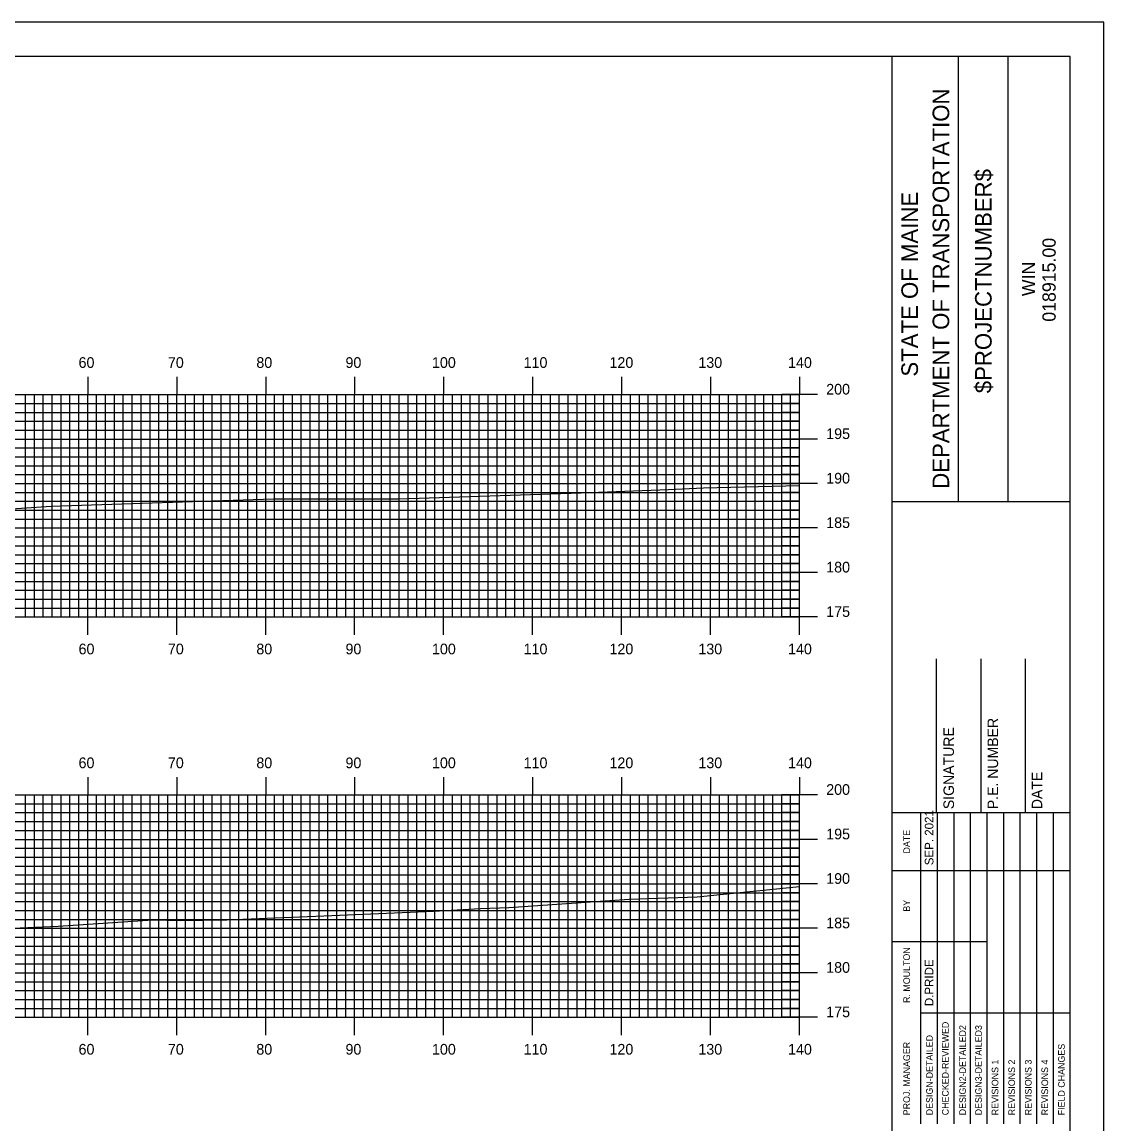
# Model space of a CAD drawing. Extents: x 1822785 to 1823129, y 442591 to 442811.
# Drawn here: x 1823003.9 to 1823125.5, y 442686.7 to 442810.5 of the extents above; entities that cross this region are included whole.
import ezdxf

# ---------------------------------------------------------------- set-up
doc = ezdxf.new("R2010")
doc.units = 0
for name, color, linetype in [('BORDER', 7, 'Continuous'), ('H_V ANNOTATION', 7, 'Continuous'), ('MAJOR', 7, 'Continuous'), ('MINOR', 7, 'Continuous'), ('PLOT BOUNDARY', 7, 'Continuous'), ('S_Roadway_Centerline', 7, 'Continuous')]:
    doc.layers.add(name, color=color, linetype=linetype)

msp = doc.modelspace()

# ---------------------------------------------------------------- linework, layer by layer
at = {"layer": 'BORDER'}
for p, q in [((1823101.68, 442596.67), (1823101.68, 442806.67)), ((1823109.14, 442756.66), (1823109.14, 442806.66)), ((1823114.73, 442756.66), (1823114.73, 442806.66)), ((1823101.68, 442756.65), (1823121.68, 442756.65)), ((1823106.68, 442721.67), (1823106.68, 442738.97)), ((1823111.68, 442721.67), (1823111.68, 442738.97)), ((1823116.68, 442721.67), (1823116.68, 442738.97)), ((1823101.68, 442721.67), (1823121.68, 442721.67))]:
    msp.add_line(p, q, dxfattribs=at)
msp.add_lwpolyline([(1822801.68, 442596.67), (1823121.68, 442596.67), (1823121.68, 442806.67), (1822801.68, 442806.67)], close=True, dxfattribs=at)
for points in [[(1823104.91, 442715.17), (1823104.91, 442721.67)], [(1823106.78, 442686.68), (1823106.78, 442721.67)], [(1823108.64, 442721.67), (1823108.64, 442686.68)], [(1823110.5, 442686.68), (1823110.5, 442721.67)], [(1823112.37, 442686.68), (1823112.37, 442721.67)], [(1823114.23, 442686.68), (1823114.23, 442721.67)], [(1823116.09, 442686.68), (1823116.09, 442721.67)], [(1823117.96, 442686.68), (1823117.96, 442721.67)], [(1823119.82, 442686.68), (1823119.82, 442721.67)], [(1823104.91, 442686.68), (1823104.91, 442720.26)], [(1823101.68, 442715.17), (1823121.68, 442715.17)], [(1823101.68, 442707.17), (1823104.91, 442707.17)], [(1823104.91, 442707.17), (1823112.37, 442707.17)], [(1823104.91, 442699.17), (1823121.68, 442699.17)]]:
    msp.add_lwpolyline(points, dxfattribs=at)
at = {"layer": 'MAJOR'}
for p, q in [((1823011.28, 442770.67), (1823011.28, 442768.67)), ((1823021.28, 442770.67), (1823021.28, 442768.67)), ((1823031.28, 442770.67), (1823031.28, 442768.67)), ((1823041.28, 442770.67), (1823041.28, 442768.67)), ((1823051.28, 442770.67), (1823051.28, 442768.67)), ((1823061.28, 442770.67), (1823061.28, 442768.67)), ((1823071.28, 442770.67), (1823071.28, 442768.67)), ((1823081.28, 442770.67), (1823081.28, 442768.67)), ((1823091.28, 442770.67), (1823091.28, 442768.67)), ((1822811.28, 442768.67), (1823091.28, 442768.67)), ((1822811.28, 442768.67), (1823091.28, 442768.67)), ((1823011.28, 442743.67), (1823011.28, 442768.67)), ((1823021.28, 442743.67), (1823021.28, 442768.67)), ((1823031.28, 442743.67), (1823031.28, 442768.67)), ((1823041.28, 442743.67), (1823041.28, 442768.67)), ((1823051.28, 442743.67), (1823051.28, 442768.67)), ((1823061.28, 442743.67), (1823061.28, 442768.67)), ((1823071.28, 442743.67), (1823071.28, 442768.67)), ((1823081.28, 442743.67), (1823081.28, 442768.67)), ((1823093.29, 442768.67), (1823089.28, 442768.67)), ((1823091.28, 442743.67), (1823091.28, 442768.67)), ((1823091.28, 442743.67), (1823091.28, 442768.67)), ((1822811.28, 442763.67), (1823091.28, 442763.67)), ((1823093.29, 442763.67), (1823089.28, 442763.67)), ((1822811.28, 442758.67), (1823091.28, 442758.67)), ((1823093.29, 442758.67), (1823089.28, 442758.67)), ((1822811.28, 442753.67), (1823091.28, 442753.67)), ((1823093.29, 442753.67), (1823089.28, 442753.67)), ((1822811.28, 442748.67), (1823091.28, 442748.67)), ((1823093.29, 442748.67), (1823089.28, 442748.67)), ((1822811.28, 442743.67), (1823091.28, 442743.67)), ((1822811.28, 442743.67), (1823091.28, 442743.67)), ((1823011.28, 442741.66), (1823011.28, 442743.67)), ((1823021.28, 442741.66), (1823021.28, 442743.67)), ((1823031.28, 442741.66), (1823031.28, 442743.67)), ((1823041.28, 442741.66), (1823041.28, 442743.67)), ((1823051.28, 442741.66), (1823051.28, 442743.67)), ((1823061.28, 442741.66), (1823061.28, 442743.67)), ((1823071.28, 442741.66), (1823071.28, 442743.67)), ((1823081.28, 442741.66), (1823081.28, 442743.67)), ((1823093.29, 442743.67), (1823089.28, 442743.67)), ((1823091.28, 442741.66), (1823091.28, 442743.67)), ((1823011.28, 442725.67), (1823011.28, 442723.67)), ((1823021.28, 442725.67), (1823021.28, 442723.67)), ((1823031.28, 442725.67), (1823031.28, 442723.67)), ((1823041.28, 442725.67), (1823041.28, 442723.67)), ((1823051.28, 442725.67), (1823051.28, 442723.67)), ((1823061.28, 442725.67), (1823061.28, 442723.67)), ((1823071.28, 442725.67), (1823071.28, 442723.67)), ((1823081.28, 442725.67), (1823081.28, 442723.67)), ((1823091.28, 442725.67), (1823091.28, 442723.67)), ((1822811.28, 442723.67), (1823091.28, 442723.67)), ((1822811.28, 442723.67), (1823091.28, 442723.67)), ((1823011.28, 442698.67), (1823011.28, 442723.67)), ((1823021.28, 442698.67), (1823021.28, 442723.67)), ((1823031.28, 442698.67), (1823031.28, 442723.67)), ((1823041.28, 442698.67), (1823041.28, 442723.67)), ((1823051.28, 442698.67), (1823051.28, 442723.67)), ((1823061.28, 442698.67), (1823061.28, 442723.67)), ((1823071.28, 442698.67), (1823071.28, 442723.67)), ((1823081.28, 442698.67), (1823081.28, 442723.67)), ((1823093.29, 442723.67), (1823089.28, 442723.67)), ((1823091.28, 442698.67), (1823091.28, 442723.67)), ((1823091.28, 442698.67), (1823091.28, 442723.67)), ((1822811.28, 442718.67), (1823091.28, 442718.67)), ((1823093.29, 442718.67), (1823089.28, 442718.67)), ((1822811.28, 442713.67), (1823091.28, 442713.67)), ((1823093.29, 442713.67), (1823089.28, 442713.67)), ((1822811.28, 442708.67), (1823091.28, 442708.67)), ((1823093.29, 442708.67), (1823089.28, 442708.67)), ((1822811.28, 442703.67), (1823091.28, 442703.67)), ((1823093.29, 442703.67), (1823089.28, 442703.67)), ((1822811.28, 442698.67), (1823091.28, 442698.67)), ((1822811.28, 442698.67), (1823091.28, 442698.67)), ((1823011.28, 442696.66), (1823011.28, 442698.67)), ((1823021.28, 442696.66), (1823021.28, 442698.67)), ((1823031.28, 442696.66), (1823031.28, 442698.67)), ((1823041.28, 442696.66), (1823041.28, 442698.67)), ((1823051.28, 442696.66), (1823051.28, 442698.67)), ((1823061.28, 442696.66), (1823061.28, 442698.67)), ((1823071.28, 442696.66), (1823071.28, 442698.67)), ((1823081.28, 442696.66), (1823081.28, 442698.67)), ((1823093.29, 442698.67), (1823089.28, 442698.67)), ((1823091.28, 442696.66), (1823091.28, 442698.67))]:
    msp.add_line(p, q, dxfattribs=at)
at = {"layer": 'MINOR'}
for p, q in [((1823004.28, 442743.67), (1823004.28, 442768.67)), ((1823005.28, 442743.67), (1823005.28, 442768.67)), ((1823006.28, 442743.67), (1823006.28, 442768.67)), ((1823007.28, 442743.67), (1823007.28, 442768.67)), ((1823008.28, 442743.67), (1823008.28, 442768.67)), ((1823009.28, 442743.67), (1823009.28, 442768.67)), ((1823010.28, 442743.67), (1823010.28, 442768.67)), ((1823012.28, 442743.67), (1823012.28, 442768.67)), ((1823013.28, 442743.67), (1823013.28, 442768.67)), ((1823014.28, 442743.67), (1823014.28, 442768.67)), ((1823015.28, 442743.67), (1823015.28, 442768.67)), ((1823016.28, 442743.67), (1823016.28, 442768.67)), ((1823017.28, 442743.67), (1823017.28, 442768.67)), ((1823018.28, 442743.67), (1823018.28, 442768.67)), ((1823019.28, 442743.67), (1823019.28, 442768.67)), ((1823020.28, 442743.67), (1823020.28, 442768.67)), ((1823022.28, 442743.67), (1823022.28, 442768.67)), ((1823023.28, 442743.67), (1823023.28, 442768.67)), ((1823024.28, 442743.67), (1823024.28, 442768.67)), ((1823025.28, 442743.67), (1823025.28, 442768.67)), ((1823026.28, 442743.67), (1823026.28, 442768.67)), ((1823027.28, 442743.67), (1823027.28, 442768.67)), ((1823028.28, 442743.67), (1823028.28, 442768.67)), ((1823029.28, 442743.67), (1823029.28, 442768.67)), ((1823030.28, 442743.67), (1823030.28, 442768.67)), ((1823032.28, 442743.67), (1823032.28, 442768.67)), ((1823033.28, 442743.67), (1823033.28, 442768.67)), ((1823034.28, 442743.67), (1823034.28, 442768.67)), ((1823035.28, 442743.67), (1823035.28, 442768.67)), ((1823036.28, 442743.67), (1823036.28, 442768.67)), ((1823037.28, 442743.67), (1823037.28, 442768.67)), ((1823038.28, 442743.67), (1823038.28, 442768.67)), ((1823039.28, 442743.67), (1823039.28, 442768.67)), ((1823040.28, 442743.67), (1823040.28, 442768.67)), ((1823042.28, 442743.67), (1823042.28, 442768.67)), ((1823043.28, 442743.67), (1823043.28, 442768.67)), ((1823044.28, 442743.67), (1823044.28, 442768.67)), ((1823045.28, 442743.67), (1823045.28, 442768.67)), ((1823046.28, 442743.67), (1823046.28, 442768.67)), ((1823047.28, 442743.67), (1823047.28, 442768.67)), ((1823048.28, 442743.67), (1823048.28, 442768.67)), ((1823049.28, 442743.67), (1823049.28, 442768.67)), ((1823050.28, 442743.67), (1823050.28, 442768.67)), ((1823052.28, 442743.67), (1823052.28, 442768.67)), ((1823053.28, 442743.67), (1823053.28, 442768.67)), ((1823054.28, 442743.67), (1823054.28, 442768.67)), ((1823055.28, 442743.67), (1823055.28, 442768.67)), ((1823056.28, 442743.67), (1823056.28, 442768.67)), ((1823057.28, 442743.67), (1823057.28, 442768.67)), ((1823058.28, 442743.67), (1823058.28, 442768.67)), ((1823059.28, 442743.67), (1823059.28, 442768.67)), ((1823060.28, 442743.67), (1823060.28, 442768.67)), ((1823062.28, 442743.67), (1823062.28, 442768.67)), ((1823063.28, 442743.67), (1823063.28, 442768.67)), ((1823064.28, 442743.67), (1823064.28, 442768.67)), ((1823065.28, 442743.67), (1823065.28, 442768.67)), ((1823066.28, 442743.67), (1823066.28, 442768.67)), ((1823067.28, 442743.67), (1823067.28, 442768.67)), ((1823068.28, 442743.67), (1823068.28, 442768.67)), ((1823069.28, 442743.67), (1823069.28, 442768.67)), ((1823070.28, 442743.67), (1823070.28, 442768.67)), ((1823072.28, 442743.67), (1823072.28, 442768.67)), ((1823073.28, 442743.67), (1823073.28, 442768.67)), ((1823074.28, 442743.67), (1823074.28, 442768.67)), ((1823075.28, 442743.67), (1823075.28, 442768.67)), ((1823076.28, 442743.67), (1823076.28, 442768.67)), ((1823077.28, 442743.67), (1823077.28, 442768.67)), ((1823078.28, 442743.67), (1823078.28, 442768.67)), ((1823079.28, 442743.67), (1823079.28, 442768.67)), ((1823080.28, 442743.67), (1823080.28, 442768.67)), ((1823082.28, 442743.67), (1823082.28, 442768.67)), ((1823083.28, 442743.67), (1823083.28, 442768.67)), ((1823084.28, 442743.67), (1823084.28, 442768.67)), ((1823085.28, 442743.67), (1823085.28, 442768.67)), ((1823086.28, 442743.67), (1823086.28, 442768.67)), ((1823087.28, 442743.67), (1823087.28, 442768.67)), ((1823088.28, 442743.67), (1823088.28, 442768.67)), ((1823089.28, 442743.67), (1823089.28, 442768.67)), ((1823090.28, 442743.67), (1823090.28, 442768.67)), ((1822811.28, 442767.67), (1823091.28, 442767.67)), ((1823091.28, 442767.67), (1823089.28, 442767.67)), ((1822811.28, 442766.67), (1823091.28, 442766.67)), ((1823091.28, 442766.67), (1823089.28, 442766.67)), ((1822811.28, 442765.67), (1823091.28, 442765.67)), ((1823091.28, 442765.67), (1823089.28, 442765.67)), ((1822811.28, 442764.67), (1823091.28, 442764.67)), ((1823091.28, 442764.67), (1823089.28, 442764.67)), ((1822811.28, 442762.67), (1823091.28, 442762.67)), ((1823091.28, 442762.67), (1823089.28, 442762.67)), ((1822811.28, 442761.67), (1823091.28, 442761.67)), ((1823091.28, 442761.67), (1823089.28, 442761.67)), ((1822811.28, 442760.67), (1823091.28, 442760.67)), ((1823091.28, 442760.67), (1823089.28, 442760.67)), ((1822811.28, 442759.67), (1823091.28, 442759.67)), ((1823091.28, 442759.67), (1823089.28, 442759.67)), ((1822811.28, 442757.67), (1823091.28, 442757.67)), ((1823091.28, 442757.67), (1823089.28, 442757.67)), ((1822811.28, 442756.67), (1823091.28, 442756.67)), ((1823091.28, 442756.67), (1823089.28, 442756.67)), ((1822811.28, 442755.67), (1823091.28, 442755.67)), ((1823091.28, 442755.67), (1823089.28, 442755.67)), ((1822811.28, 442754.67), (1823091.28, 442754.67)), ((1823091.28, 442754.67), (1823089.28, 442754.67)), ((1822811.28, 442752.67), (1823091.28, 442752.67)), ((1823091.28, 442752.67), (1823089.28, 442752.67)), ((1822811.28, 442751.67), (1823091.28, 442751.67)), ((1823091.28, 442751.67), (1823089.28, 442751.67)), ((1822811.28, 442750.67), (1823091.28, 442750.67)), ((1823091.28, 442750.67), (1823089.28, 442750.67)), ((1822811.28, 442749.67), (1823091.28, 442749.67)), ((1823091.28, 442749.67), (1823089.28, 442749.67)), ((1822811.28, 442747.67), (1823091.28, 442747.67)), ((1823091.28, 442747.67), (1823089.28, 442747.67)), ((1822811.28, 442746.67), (1823091.28, 442746.67)), ((1823091.28, 442746.67), (1823089.28, 442746.67)), ((1822811.28, 442745.67), (1823091.28, 442745.67)), ((1823091.28, 442745.67), (1823089.28, 442745.67)), ((1822811.28, 442744.67), (1823091.28, 442744.67)), ((1823091.28, 442744.67), (1823089.28, 442744.67)), ((1823004.28, 442698.67), (1823004.28, 442723.67)), ((1823005.28, 442698.67), (1823005.28, 442723.67)), ((1823006.28, 442698.67), (1823006.28, 442723.67)), ((1823007.28, 442698.67), (1823007.28, 442723.67)), ((1823008.28, 442698.67), (1823008.28, 442723.67)), ((1823009.28, 442698.67), (1823009.28, 442723.67)), ((1823010.28, 442698.67), (1823010.28, 442723.67)), ((1823012.28, 442698.67), (1823012.28, 442723.67)), ((1823013.28, 442698.67), (1823013.28, 442723.67)), ((1823014.28, 442698.67), (1823014.28, 442723.67)), ((1823015.28, 442698.67), (1823015.28, 442723.67)), ((1823016.28, 442698.67), (1823016.28, 442723.67)), ((1823017.28, 442698.67), (1823017.28, 442723.67)), ((1823018.28, 442698.67), (1823018.28, 442723.67)), ((1823019.28, 442698.67), (1823019.28, 442723.67)), ((1823020.28, 442698.67), (1823020.28, 442723.67)), ((1823022.28, 442698.67), (1823022.28, 442723.67)), ((1823023.28, 442698.67), (1823023.28, 442723.67)), ((1823024.28, 442698.67), (1823024.28, 442723.67)), ((1823025.28, 442698.67), (1823025.28, 442723.67)), ((1823026.28, 442698.67), (1823026.28, 442723.67)), ((1823027.28, 442698.67), (1823027.28, 442723.67)), ((1823028.28, 442698.67), (1823028.28, 442723.67)), ((1823029.28, 442698.67), (1823029.28, 442723.67)), ((1823030.28, 442698.67), (1823030.28, 442723.67)), ((1823032.28, 442698.67), (1823032.28, 442723.67)), ((1823033.28, 442698.67), (1823033.28, 442723.67)), ((1823034.28, 442698.67), (1823034.28, 442723.67)), ((1823035.28, 442698.67), (1823035.28, 442723.67)), ((1823036.28, 442698.67), (1823036.28, 442723.67)), ((1823037.28, 442698.67), (1823037.28, 442723.67)), ((1823038.28, 442698.67), (1823038.28, 442723.67)), ((1823039.28, 442698.67), (1823039.28, 442723.67)), ((1823040.28, 442698.67), (1823040.28, 442723.67)), ((1823042.28, 442698.67), (1823042.28, 442723.67)), ((1823043.28, 442698.67), (1823043.28, 442723.67)), ((1823044.28, 442698.67), (1823044.28, 442723.67)), ((1823045.28, 442698.67), (1823045.28, 442723.67)), ((1823046.28, 442698.67), (1823046.28, 442723.67)), ((1823047.28, 442698.67), (1823047.28, 442723.67)), ((1823048.28, 442698.67), (1823048.28, 442723.67)), ((1823049.28, 442698.67), (1823049.28, 442723.67)), ((1823050.28, 442698.67), (1823050.28, 442723.67)), ((1823052.28, 442698.67), (1823052.28, 442723.67)), ((1823053.28, 442698.67), (1823053.28, 442723.67)), ((1823054.28, 442698.67), (1823054.28, 442723.67)), ((1823055.28, 442698.67), (1823055.28, 442723.67)), ((1823056.28, 442698.67), (1823056.28, 442723.67)), ((1823057.28, 442698.67), (1823057.28, 442723.67)), ((1823058.28, 442698.67), (1823058.28, 442723.67)), ((1823059.28, 442698.67), (1823059.28, 442723.67)), ((1823060.28, 442698.67), (1823060.28, 442723.67)), ((1823062.28, 442698.67), (1823062.28, 442723.67)), ((1823063.28, 442698.67), (1823063.28, 442723.67)), ((1823064.28, 442698.67), (1823064.28, 442723.67)), ((1823065.28, 442698.67), (1823065.28, 442723.67)), ((1823066.28, 442698.67), (1823066.28, 442723.67)), ((1823067.28, 442698.67), (1823067.28, 442723.67)), ((1823068.28, 442698.67), (1823068.28, 442723.67)), ((1823069.28, 442698.67), (1823069.28, 442723.67)), ((1823070.28, 442698.67), (1823070.28, 442723.67)), ((1823072.28, 442698.67), (1823072.28, 442723.67)), ((1823073.28, 442698.67), (1823073.28, 442723.67)), ((1823074.28, 442698.67), (1823074.28, 442723.67)), ((1823075.28, 442698.67), (1823075.28, 442723.67)), ((1823076.28, 442698.67), (1823076.28, 442723.67)), ((1823077.28, 442698.67), (1823077.28, 442723.67)), ((1823078.28, 442698.67), (1823078.28, 442723.67)), ((1823079.28, 442698.67), (1823079.28, 442723.67)), ((1823080.28, 442698.67), (1823080.28, 442723.67)), ((1823082.28, 442698.67), (1823082.28, 442723.67)), ((1823083.28, 442698.67), (1823083.28, 442723.67)), ((1823084.28, 442698.67), (1823084.28, 442723.67)), ((1823085.28, 442698.67), (1823085.28, 442723.67)), ((1823086.28, 442698.67), (1823086.28, 442723.67)), ((1823087.28, 442698.67), (1823087.28, 442723.67)), ((1823088.28, 442698.67), (1823088.28, 442723.67)), ((1823089.28, 442698.67), (1823089.28, 442723.67)), ((1823090.28, 442698.67), (1823090.28, 442723.67)), ((1822811.28, 442722.67), (1823091.28, 442722.67)), ((1822811.28, 442721.67), (1823091.28, 442721.67)), ((1823091.28, 442722.67), (1823089.28, 442722.67)), ((1823091.28, 442721.67), (1823089.28, 442721.67)), ((1822811.28, 442720.67), (1823091.28, 442720.67)), ((1823091.28, 442720.67), (1823089.28, 442720.67)), ((1822811.28, 442719.67), (1823091.28, 442719.67)), ((1823091.28, 442719.67), (1823089.28, 442719.67)), ((1822811.28, 442717.67), (1823091.28, 442717.67)), ((1822811.28, 442716.67), (1823091.28, 442716.67)), ((1823091.28, 442717.67), (1823089.28, 442717.67)), ((1823091.28, 442716.67), (1823089.28, 442716.67)), ((1822811.28, 442715.67), (1823091.28, 442715.67)), ((1823091.28, 442715.67), (1823089.28, 442715.67)), ((1822811.28, 442714.67), (1823091.28, 442714.67)), ((1823091.28, 442714.67), (1823089.28, 442714.67)), ((1822811.28, 442712.67), (1823091.28, 442712.67)), ((1822811.28, 442711.67), (1823091.28, 442711.67)), ((1823091.28, 442712.67), (1823089.28, 442712.67)), ((1823091.28, 442711.67), (1823089.28, 442711.67)), ((1822811.28, 442710.67), (1823091.28, 442710.67)), ((1823091.28, 442710.67), (1823089.28, 442710.67)), ((1822811.28, 442709.67), (1823091.28, 442709.67)), ((1823091.28, 442709.67), (1823089.28, 442709.67)), ((1822811.28, 442707.67), (1823091.28, 442707.67)), ((1822811.28, 442706.67), (1823091.28, 442706.67)), ((1823091.28, 442707.67), (1823089.28, 442707.67)), ((1823091.28, 442706.67), (1823089.28, 442706.67)), ((1822811.28, 442705.67), (1823091.28, 442705.67)), ((1823091.28, 442705.67), (1823089.28, 442705.67)), ((1822811.28, 442704.67), (1823091.28, 442704.67)), ((1823091.28, 442704.67), (1823089.28, 442704.67)), ((1822811.28, 442702.67), (1823091.28, 442702.67)), ((1822811.28, 442701.67), (1823091.28, 442701.67)), ((1823091.28, 442702.67), (1823089.28, 442702.67)), ((1823091.28, 442701.67), (1823089.28, 442701.67)), ((1822811.28, 442700.67), (1823091.28, 442700.67)), ((1823091.28, 442700.67), (1823089.28, 442700.67)), ((1822811.28, 442699.67), (1823091.28, 442699.67)), ((1823091.28, 442699.67), (1823089.28, 442699.67))]:
    msp.add_line(p, q, dxfattribs=at)
at = {"layer": 'PLOT BOUNDARY'}
msp.add_lwpolyline([(1822785.5, 442590.55), (1823125.5, 442590.55), (1823125.5, 442810.55), (1822785.5, 442810.55)], close=True, dxfattribs=at)
at = {"layer": 'S_Roadway_Centerline'}
for points in [[(1822993.8, 442755.24), (1823007.16, 442756.13), (1823032.15, 442756.93), (1823046.25, 442756.94), (1823066.75, 442757.63), (1823076.57, 442757.99), (1823080.48, 442758.19), (1823091.28, 442758.43)], [(1823003.7, 442708.74), (1823007.94, 442708.92), (1823018.58, 442709.61), (1823021.74, 442709.56), (1823026.92, 442709.63), (1823038.7, 442710.11), (1823050.16, 442710.58), (1823055.44, 442710.9), (1823058.59, 442711), (1823072.13, 442711.94), (1823079.77, 442712.21), (1823091.28, 442713.38)]]:
    msp.add_lwpolyline(points, dxfattribs=at)

# ---------------------------------------------------------------- texts
at = {"layer": 'BORDER'}
for s, height, p in [('DEPARTMENT OF TRANSPORTATION', 1.8635, (1823108.1, 442758.08)), ('$PROJECTNUMBER$', 1.8635, (1823112.87, 442768.82)), ('STATE OF MAINE', 1.8635, (1823104.59, 442770.69)), ('018915.00', 1.491, (1823120.07, 442776.86)), ('WIN', 1.491, (1823117.76, 442779.73)), ('P.E. NUMBER', 1.1811, (1823113.6, 442722.06)), ('SIGNATURE', 1.181, (1823108.64, 442722.06)), ('DATE', 1.181, (1823118.56, 442722.06)), ('SEP. 2021', 0.969, (1823106.33, 442715.76)), ('DATE', 0.743, (1823103.69, 442717.08)), ('BY', 0.743, (1823103.69, 442710.54)), ('R. MOULTON', 0.745, (1823103.69, 442700.28)), ('D.PRIDE', 0.969, (1823106.33, 442699.92)), ('CHECKED-REVIEWED', 0.7455, (1823108.04, 442687.65)), ('DESIGN2-DETAILED2', 0.7455, (1823109.98, 442687.65)), ('DESIGN3-DETAILED3', 0.7455, (1823111.77, 442687.65)), ('PROJ. MANAGER', 0.7455, (1823103.69, 442687.65)), ('DESIGN-DETAILED', 0.7455, (1823106.26, 442687.65)), ('FIELD CHANGES', 0.7455, (1823121.09, 442687.65)), ('REVISIONS 1', 0.7455, (1823113.63, 442687.65)), ('REVISIONS 2', 0.7455, (1823115.5, 442687.65)), ('REVISIONS 3', 0.7455, (1823117.36, 442687.65)), ('REVISIONS 4', 0.7455, (1823119.22, 442687.65))]:
    msp.add_text(s, height=height, rotation=90, dxfattribs=at).set_placement(p)
at = {"layer": 'H_V ANNOTATION'}
for s, p in [('60', (1823010.25, 442771.67)), ('70', (1823020.29, 442771.67)), ('80', (1823030.23, 442771.67)), ('90', (1823040.25, 442771.67)), ('100', (1823049.97, 442771.67)), ('110', (1823060.27, 442771.67)), ('120', (1823069.92, 442771.67)), ('130', (1823079.91, 442771.67)), ('140', (1823089.99, 442771.67)), ('200', (1823094.28, 442768.67)), ('195', (1823094.28, 442763.67)), ('190', (1823094.28, 442758.67)), ('185', (1823094.28, 442753.67)), ('180', (1823094.28, 442748.67)), ('175', (1823094.28, 442743.67)), ('60', (1823010.25, 442739.47)), ('70', (1823020.29, 442739.47)), ('80', (1823030.23, 442739.47)), ('90', (1823040.25, 442739.47)), ('100', (1823049.97, 442739.47)), ('110', (1823060.27, 442739.47)), ('120', (1823069.92, 442739.47)), ('130', (1823079.91, 442739.47)), ('140', (1823089.99, 442739.47)), ('60', (1823010.25, 442726.67)), ('70', (1823020.29, 442726.67)), ('80', (1823030.23, 442726.67)), ('90', (1823040.25, 442726.67)), ('100', (1823049.97, 442726.67)), ('110', (1823060.27, 442726.67)), ('120', (1823069.92, 442726.67)), ('130', (1823079.91, 442726.67)), ('140', (1823089.99, 442726.67)), ('200', (1823094.28, 442723.67)), ('195', (1823094.28, 442718.67)), ('190', (1823094.28, 442713.67)), ('185', (1823094.28, 442708.67)), ('180', (1823094.28, 442703.67)), ('175', (1823094.28, 442698.67)), ('60', (1823010.25, 442694.47)), ('70', (1823020.29, 442694.47)), ('80', (1823030.23, 442694.47)), ('90', (1823040.25, 442694.47)), ('100', (1823049.97, 442694.47)), ('110', (1823060.27, 442694.47)), ('120', (1823069.92, 442694.47)), ('130', (1823079.91, 442694.47)), ('140', (1823089.99, 442694.47))]:
    msp.add_text(s, height=1.2, dxfattribs=at).set_placement(p)

doc.saveas('drawing.dxf')
